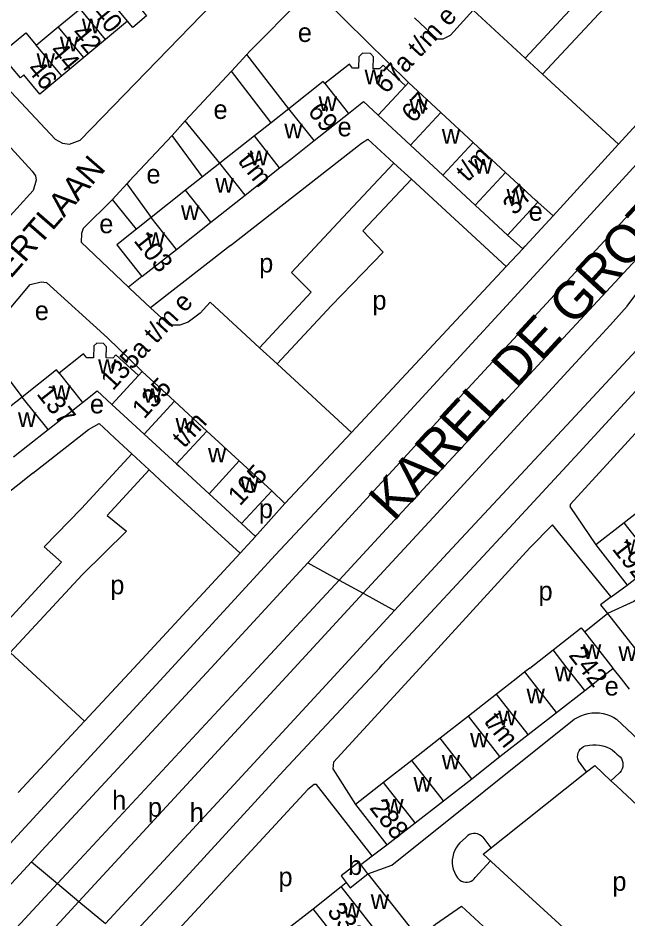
# Model space of a CAD drawing. Extents: x 159045 to 160918, y 380454 to 382516.
# Drawn here: x 159658 to 159786.4, y 381697.2 to 381886.8 of the extents above; entities that cross this region are included whole.
import ezdxf

# ---------------------------------------------------------------- set-up
doc = ezdxf.new("R2010")
doc.units = 0
for name, color, linetype in [('BLT_Basislijn', 7, 'Continuous'), ('BLT_Bebouwing', 7, 'Continuous'), ('BLT_Centroide', 7, 'Continuous'), ('BLT_Huisnummer', 7, 'Continuous'), ('BLT_Huisnummer_ tussenligend', 7, 'Continuous'), ('BLT_Huisnummer_reeks', 7, 'Continuous'), ('BLT_Onderverdeling_panden', 7, 'Continuous'), ('BLT_Straatnaam', 7, 'Continuous'), ('BLT_Straatnaam_hoofdweg', 7, 'Continuous'), ('BLT_Vlakafsluiter', 7, 'Continuous')]:
    doc.layers.add(name, color=color, linetype=linetype)

msp = doc.modelspace()

# ---------------------------------------------------------------- linework, layer by layer
at = {"layer": 'BLT_Basislijn'}
for p, q in [((159706.18, 381879.18), (159702.89, 381875.65)), ((159714.98, 381867.75), (159706.18, 381879.18)), ((159764.73, 381878.39), (159768.4, 381875)), ((159702.89, 381875.65), (159693.18, 381865.19)), ((159711.24, 381864.8), (159702.89, 381875.65)), ((159768.4, 381875), (159784.38, 381860.25)), ((159693.18, 381865.19), (159690.43, 381862.1)), ((159700.49, 381856.3), (159693.18, 381865.19)), ((159696.84, 381853.41), (159690.43, 381862.1)), ((159770.67, 381845.22), (159784.38, 381860.25)), ((159740.8, 381852.9), (159760.77, 381834.53)), ((159680.88, 381851.94), (159677.84, 381848.61)), ((159680.88, 381851.94), (159686, 381844.84)), ((159682.89, 381842.38), (159677.84, 381848.61)), ((159761.03, 381841.14), (159764.24, 381838.28)), ((159702.69, 381838.97), (159685.85, 381825.85)), ((159760.77, 381834.53), (159764.24, 381838.28)), ((159728.17, 381799.61), (159760.77, 381834.53)), ((159684.07, 381832.39), (159681.23, 381830.16)), ((159650.13, 381818.42), (159658.86, 381807.04)), ((159728.17, 381799.61), (159712.52, 381814.05)), ((159675.98, 381800.64), (159678.38, 381798.4)), ((159714.17, 381784.62), (159728.17, 381799.61)), ((159681.91, 381795.12), (159685.57, 381791.72)), ((159685.57, 381791.72), (159688.89, 381788.62)), ((159661.08, 381790.99), (159658.54, 381788.99)), ((159658.54, 381788.99), (159628.95, 381765.71)), ((159688.89, 381788.62), (159704.73, 381774.16)), ((159714.17, 381784.62), (159711.39, 381787.31)), ((159705.01, 381780.42), (159707.97, 381777.68)), ((159704.73, 381774.16), (159707.97, 381777.68)), ((159682.33, 381750), (159704.73, 381774.16)), ((159690.32, 381750), (159712.2, 381773.81)), ((159698.56, 381750), (159719, 381772.11)), ((159782.85, 381764.98), (159786.23, 381767.47)), ((159671.95, 381738.82), (159656.35, 381753.26)), ((159656.27, 381712.96), (159690.32, 381750)), ((159663, 381711.56), (159698.56, 381750)), ((159670.09, 381708.68), (159708.4, 381750)), ((159671.95, 381738.82), (159682.33, 381750)), ((159675.01, 381705.41), (159716.13, 381750)), ((159726.1, 381750), (159721.98, 381745.55)), ((159734.05, 381750), (159734.66, 381750.65)), ((159657.97, 381723.8), (159671.95, 381738.82)), ((159783.95, 381739.24), (159817.59, 381707.64)), ((159777.68, 381728.11), (159775.96, 381730.47)), ((159755.89, 381710.79), (159777.68, 381728.11)), ((159784.55, 381727.86), (159782.8, 381726.24)), ((159782.8, 381726.24), (159783.95, 381725.16)), ((159752.2, 381714.25), (159751.01, 381713.19)), ((159755.82, 381714.38), (159757.55, 381712.11)), ((159732.54, 381710.43), (159735.63, 381712.76)), ((159730.12, 381708.6), (159732.54, 381710.43)), ((159755.89, 381710.79), (159765.48, 381702.01)), ((159754.2, 381705.88), (159757.44, 381709.38))]:
    msp.add_line(p, q, dxfattribs=at)
for points in [[(159671.87, 381915.68), (159677.46, 381909.03), (159676.79, 381907.98), (159673.6, 381905.32), (159649.48, 381885.21), (159647.67, 381882.98), (159648.15, 381880.73), (159648.65, 381880.03), (159656.52, 381871.2), (159665.8, 381861.36), (159667.35, 381860.48), (159668.8, 381860.27), (159671.09, 381861.15), (159710.49, 381901.86), (159730.69, 381922.64), (159732.46, 381924.74), (159732.71, 381927.22), (159731.89, 381928.43)], [(159793.21, 381917.44), (159782.4, 381905.92), (159771.73, 381894.65), (159775.99, 381890.48), (159764.73, 381878.39)], [(159796.88, 381914.05), (159786.67, 381903.16), (159790.93, 381898.65), (159780.26, 381887.73), (159768.4, 381875)], [(159784.38, 381860.25), (159816.73, 381895.72)], [(159740.18, 381873.28), (159722.47, 381890.74), (159720.66, 381891.75), (159718.65, 381891.67), (159717.52, 381890.71), (159706.8, 381879.85), (159706.18, 381879.18)], [(159741.44, 381886.87), (159746.16, 381882.45), (159747.48, 381882.45), (159749.01, 381883.21), (159753.81, 381888.48), (159764.73, 381878.39)], [(159782.63, 381822.15), (159786.21, 381826.18), (159794.99, 381837.92), (159804.12, 381849.5), (159810.38, 381856.62), (159829.29, 381876.17), (159836.63, 381883.45)], [(159771.01, 381817.53), (159804.44, 381853.6), (159828.09, 381881.26)], [(159644.57, 381872.44), (159660.96, 381854.63), (159661.66, 381853.63), (159661.82, 381852.68), (159661.18, 381850.54), (159599.18, 381782.35), (159598.21, 381781.87), (159596.31, 381781.68), (159595.12, 381782.25), (159574.14, 381801.25), (159574.2, 381802.01), (159603.01, 381830.59)], [(159690.43, 381862.1), (159681.37, 381852.48), (159680.88, 381851.94)], [(159702.69, 381838.97), (159730.26, 381860.52), (159731.63, 381861.33), (159737.12, 381856.28)], [(159737.12, 381856.28), (159726.33, 381844.84), (159715.57, 381833.25), (159719.68, 381829.1), (159708.84, 381817.44)], [(159712.2, 381773.81), (159735.79, 381799.05), (159776.92, 381843.76), (159788.98, 381856.91)], [(159737.12, 381856.28), (159740.8, 381852.9)], [(159740.8, 381852.9), (159730.58, 381842.06), (159734.86, 381837.57), (159723.94, 381826.34), (159712.52, 381814.05)], [(159719, 381772.11), (159749.25, 381805.09), (159794.4, 381853.97)], [(159677.84, 381848.61), (159671.68, 381842.5), (159671.31, 381841.51), (159671.25, 381839.66), (159681.23, 381830.16)], [(159770.67, 381845.22), (159767.42, 381848.04)], [(159764.24, 381838.28), (159764.76, 381838.84), (159770.67, 381845.22)], [(159832.6, 381819.29), (159832.39, 381819.64), (159823.22, 381831.13), (159820.2, 381834.34), (159819.82, 381834.26), (159774.32, 381784.48), (159774.15, 381783.98), (159779.62, 381775.9)], [(159809.37, 381831.59), (159776.1, 381795.36), (159761.41, 381779.42), (159734.66, 381750.65)], [(159650.13, 381818.42), (159650.71, 381819.07), (159660.55, 381830.73), (159662.87, 381831.27), (159663.98, 381831.15), (159676.84, 381819.54), (159684.1, 381812.42)], [(159681.23, 381830.16), (159681.43, 381829.97), (159685.85, 381825.85)], [(159798.24, 381827.72), (159773.47, 381801.08), (159748.42, 381774.17), (159737.26, 381762.08)], [(159708.84, 381817.44), (159698.46, 381827.03), (159696.29, 381824.71), (159693.81, 381822.84), (159692.02, 381822.16), (159689.89, 381822.16), (159685.85, 381825.85)], [(159730.62, 381765.73), (159745.34, 381781.68), (159782.63, 381822.15)], [(159712.52, 381814.05), (159708.84, 381817.44)], [(159725.56, 381768.51), (159739.71, 381783.76), (159771.01, 381817.53)], [(159661.08, 381790.99), (159672.79, 381800.2), (159675.08, 381801.47), (159675.98, 381800.64)], [(159678.38, 381798.4), (159681.91, 381795.12)], [(159681.91, 381795.12), (159671.33, 381783.61), (159663.46, 381775.49), (159667.15, 381772.28), (159652.68, 381756.66)], [(159825.93, 381794.08), (159787.61, 381763.98), (159782.09, 381761.45)], [(159685.57, 381791.72), (159676.72, 381782.08), (159680.78, 381778.79), (159671.49, 381769.61), (159656.35, 381753.26)], [(159707.97, 381777.68), (159708.14, 381777.87), (159708.36, 381778.15), (159714.17, 381784.62)], [(159782.85, 381764.98), (159770.49, 381780.16), (159765.75, 381775.32), (159742.54, 381750)], [(159708.4, 381750), (159725.56, 381768.51)], [(159716.13, 381750), (159730.62, 381765.73)], [(159782.85, 381764.98), (159780.6, 381763.32), (159782.09, 381761.45)], [(159737.26, 381762.08), (159726.1, 381750)], [(159680.83, 381692.5), (159691.75, 381704.21), (159713.87, 381728.34), (159734.05, 381750)], [(159742.54, 381750), (159724.39, 381730.21), (159724.25, 381728.74), (159728.99, 381721.27)], [(159721.98, 381745.55), (159703.4, 381725.41), (159676.38, 381696.21)], [(159775.09, 381739.2), (159775.77, 381739.61), (159776.48, 381739.96), (159777.23, 381740.23), (159778.01, 381740.42), (159778.79, 381740.54), (159779.59, 381740.58), (159780.38, 381740.53), (159781.17, 381740.41), (159781.94, 381740.21), (159782.69, 381739.93), (159783.4, 381739.58), (159783.95, 381739.24)], [(159731.64, 381706.66), (159736.65, 381708.5), (159775.09, 381739.2)], [(159775.96, 381730.47), (159775.83, 381730.88), (159775.78, 381731.31), (159775.81, 381731.74), (159775.91, 381732.16), (159776.09, 381732.56), (159776.34, 381732.91), (159776.65, 381733.21), (159777.02, 381733.45), (159777.41, 381733.62), (159777.84, 381733.72), (159778.3, 381733.73)], [(159778.3, 381733.73), (159779, 381733.82), (159779.71, 381733.84), (159780.42, 381733.77), (159781.11, 381733.62), (159781.78, 381733.4), (159782.42, 381733.1), (159783.03, 381732.74), (159783.59, 381732.3), (159784.05, 381731.86)], [(159784.05, 381731.86), (159784.42, 381731.61), (159784.74, 381731.3), (159784.99, 381730.93), (159785.18, 381730.53), (159785.3, 381730.1), (159785.33, 381729.65), (159785.29, 381729.21), (159785.17, 381728.78), (159784.97, 381728.38), (159784.7, 381728.02), (159784.55, 381727.86)], [(159777.68, 381728.11), (159779.43, 381729.48), (159782.8, 381726.24)], [(159732.54, 381710.43), (159720.78, 381725.45), (159720.34, 381725.49), (159718.96, 381724.43), (159685.73, 381688.42)], [(159783.95, 381725.16), (159807.15, 381703.51), (159809.15, 381705.75)], [(159755.82, 381714.38), (159755.5, 381714.68), (159755.13, 381714.91), (159754.73, 381715.07), (159754.31, 381715.15), (159753.87, 381715.16), (159753.45, 381715.08), (159753.04, 381714.93), (159752.67, 381714.71), (159752.35, 381714.42), (159752.2, 381714.25)], [(159751.01, 381713.19), (159750.57, 381712.69), (159750.19, 381712.14), (159749.88, 381711.54), (159749.64, 381710.92), (159749.48, 381710.27), (159749.39, 381709.61), (159749.39, 381708.94), (159749.46, 381708.27), (159749.62, 381707.62), (159749.85, 381706.99), (159750.15, 381706.4), (159750.52, 381705.84), (159750.7, 381705.63)], [(159660.8, 381709.18), (159663, 381711.56)], [(159584.99, 381627.52), (159591.57, 381638.08), (159594.19, 381641.64), (159608.73, 381656.8), (159611.67, 381659.27), (159619.4, 381664.53), (159622.8, 381668.09), (159660.8, 381709.18)], [(159666.3, 381704.6), (159670.09, 381708.68)], [(159598.4, 381631.14), (159631.77, 381667.36), (159666.3, 381704.6)], [(159670.81, 381700.85), (159675.01, 381705.41)], [(159750.7, 381705.63), (159751, 381705.34), (159751.36, 381705.12), (159751.75, 381704.96), (159752.16, 381704.89), (159752.58, 381704.89), (159752.99, 381704.97), (159753.38, 381705.13), (159753.73, 381705.36), (159754.03, 381705.65), (159754.2, 381705.88)], [(159612.46, 381637.63), (159633.9, 381660.83), (159670.81, 381700.85)], [(159765.48, 381702.01), (159787.17, 381682.15), (159783.55, 381678.28)], [(159743.87, 381694.45), (159745.88, 381696.05), (159751.35, 381699.86), (159783.3, 381670.38)]]:
    msp.add_lwpolyline(points, dxfattribs=at)
at = {"layer": 'BLT_Bebouwing'}
for p, q in [((159666.43, 381884.96), (159671.05, 381888.8)), ((159661.81, 381881.12), (159666.43, 381884.96)), ((159681.04, 381886.18), (159676.42, 381882.34)), ((159676.42, 381882.34), (159671.8, 381878.5)), ((159671.8, 381878.5), (159667.17, 381874.66)), ((159740.18, 381873.28), (159739.52, 381872.57)), ((159746.99, 381866.97), (159740.18, 381873.28)), ((159714.98, 381867.75), (159711.24, 381864.8)), ((159720.29, 381861.03), (159727.54, 381866.76)), ((159733.79, 381866.38), (159740.6, 381860.07)), ((159753.8, 381860.66), (159746.99, 381866.97)), ((159711.24, 381864.8), (159707.73, 381862.03)), ((159707.73, 381862.03), (159700.49, 381856.3)), ((159740.6, 381860.07), (159747.41, 381853.76)), ((159760.61, 381854.35), (159753.8, 381860.66)), ((159700.49, 381856.3), (159696.84, 381853.41)), ((159705.81, 381849.58), (159713.05, 381855.3)), ((159766.9, 381848.52), (159760.61, 381854.35)), ((159696.84, 381853.41), (159693.25, 381850.57)), ((159693.25, 381850.57), (159686, 381844.84)), ((159698.56, 381843.85), (159705.81, 381849.58)), ((159767.42, 381848.04), (159766.9, 381848.52)), ((159754.22, 381847.45), (159761.03, 381841.14)), ((159761.03, 381841.14), (159767.42, 381848.04)), ((159686, 381844.84), (159682.89, 381842.38)), ((159691.32, 381838.12), (159698.56, 381843.85)), ((159684.07, 381832.39), (159691.32, 381838.12)), ((159684.1, 381812.42), (159683.31, 381811.57)), ((159690.92, 381806.15), (159684.1, 381812.42)), ((159658.86, 381807.04), (159655.21, 381804.14)), ((159664.29, 381800.2), (159671.52, 381805.93)), ((159677.74, 381805.5), (159684.55, 381799.23)), ((159697.74, 381799.88), (159690.92, 381806.15)), ((159684.55, 381799.23), (159691.37, 381792.96)), ((159704.56, 381793.61), (159697.74, 381799.88)), ((159711.39, 381787.31), (159704.56, 381793.61)), ((159698.19, 381786.69), (159705.01, 381780.42)), ((159705.01, 381780.42), (159711.39, 381787.31)), ((159791.49, 381785.21), (159785.56, 381780.55)), ((159785.56, 381780.55), (159779.62, 381775.9)), ((159779.62, 381775.9), (159786.23, 381767.47)), ((159786.23, 381767.47), (159792.17, 381772.12)), ((159777.2, 381757.63), (159782.09, 381761.45)), ((159782.09, 381761.45), (159791.05, 381750)), ((159765.76, 381750), (159770.63, 381753.81)), ((159765.76, 381750), (159764.68, 381749.16)), ((159758.73, 381744.51), (159752.79, 381739.86)), ((159771.33, 381740.64), (159777.28, 381745.29)), ((159765.38, 381735.99), (159771.33, 381740.64)), ((159752.79, 381739.86), (159746.84, 381735.21)), ((159746.84, 381735.21), (159740.89, 381730.56)), ((159759.43, 381731.35), (159765.38, 381735.99)), ((159753.48, 381726.7), (159759.43, 381731.35)), ((159740.89, 381730.56), (159734.94, 381725.92)), ((159734.94, 381725.92), (159728.99, 381721.27)), ((159747.53, 381722.06), (159753.48, 381726.7)), ((159741.58, 381717.41), (159747.53, 381722.06)), ((159728.99, 381721.27), (159735.63, 381712.76)), ((159735.63, 381712.76), (159741.58, 381717.41)), ((159731.64, 381706.66), (159730.12, 381708.6)), ((159731.64, 381706.66), (159741.09, 381694.67)), ((159726.02, 381703.97), (159727.09, 381704.81)), ((159720.1, 381699.33), (159726.02, 381703.97)), ((159714.17, 381694.69), (159720.1, 381699.33))]:
    msp.add_line(p, q, dxfattribs=at)
for points in [[(159685.67, 381890.03), (159683.94, 381888.59), (159685.04, 381887.27), (159682.15, 381884.87), (159681.04, 381886.18)], [(159667.17, 381874.66), (159662.55, 381870.82), (159659.21, 381874.85), (159658.49, 381874.26), (159656.61, 381876.52), (159654.29, 381879.31), (159659.62, 381883.75), (159661.81, 381881.12)], [(159739.52, 381872.57), (159734.84, 381876.91), (159734.1, 381876.11), (159732.77, 381876.15), (159732.84, 381878.68), (159732.18, 381879.37), (159730.52, 381879.41), (159729.73, 381878.66), (159729.67, 381876.26), (159728.39, 381876.29), (159727.73, 381877.12), (159722.57, 381873.04)], [(159722.57, 381873.04), (159722.22, 381873.48), (159714.98, 381867.75)], [(159727.54, 381866.76), (159730.69, 381869.25), (159733.79, 381866.38)], [(159713.05, 381855.3), (159715.38, 381857.15), (159720.29, 381861.03)], [(159747.41, 381853.76), (159748.28, 381852.96), (159754.22, 381847.45)], [(159682.89, 381842.38), (159678.76, 381839.11), (159684.07, 381832.39)], [(159683.31, 381811.57), (159678.58, 381815.92), (159677.94, 381815.22), (159676.54, 381815.27), (159676.62, 381817.64), (159675.97, 381818.33), (159674.54, 381818.38), (159673.93, 381817.8), (159673.84, 381815.27), (159672.45, 381815.31), (159671.77, 381816.17), (159666.63, 381812.1)], [(159666.63, 381812.1), (159666.1, 381812.77), (159658.86, 381807.04)], [(159671.52, 381805.93), (159674.61, 381808.38), (159677.74, 381805.5)], [(159657.05, 381794.46), (159660.03, 381796.82), (159664.29, 381800.2)], [(159691.37, 381792.96), (159691.92, 381792.46), (159698.19, 381786.69)], [(159770.63, 381753.81), (159776.56, 381758.45), (159777.2, 381757.63)], [(159777.28, 381745.29), (159780.42, 381747.74), (159783.23, 381749.93)], [(159783.23, 381749.93), (159784.94, 381747.74), (159786.65, 381745.55)], [(159764.68, 381749.16), (159762.87, 381747.74), (159758.73, 381744.51)], [(159730.12, 381708.6), (159729.69, 381709.14), (159725.98, 381706.23), (159727.09, 381704.81)], [(159727.09, 381704.81), (159727.92, 381703.75), (159731.64, 381706.66)]]:
    msp.add_lwpolyline(points, dxfattribs=at)
at = {"layer": 'BLT_Onderverdeling_panden'}
for p, q in [((159681.04, 381886.18), (159675.68, 381892.65)), ((159676.42, 381882.34), (159671.05, 381888.8)), ((159671.8, 381878.5), (159666.43, 381884.96)), ((159667.17, 381874.66), (159661.81, 381881.12)), ((159722.57, 381873.04), (159727.54, 381866.76)), ((159739.52, 381872.57), (159733.79, 381866.38)), ((159720.29, 381861.03), (159714.98, 381867.75)), ((159740.6, 381860.07), (159746.99, 381866.97)), ((159713.05, 381855.3), (159707.73, 381862.03)), ((159747.41, 381853.76), (159753.8, 381860.66)), ((159705.81, 381849.58), (159700.49, 381856.3)), ((159754.22, 381847.45), (159760.61, 381854.35)), ((159698.56, 381843.85), (159693.25, 381850.57)), ((159691.32, 381838.12), (159686, 381844.84)), ((159666.63, 381812.1), (159671.52, 381805.93)), ((159683.31, 381811.57), (159677.74, 381805.5)), ((159664.29, 381800.2), (159658.86, 381807.04)), ((159690.92, 381806.15), (159684.55, 381799.23)), ((159697.74, 381799.88), (159691.37, 381792.96)), ((159704.56, 381793.61), (159698.19, 381786.69)), ((159792.17, 381772.12), (159785.56, 381780.55)), ((159777.2, 381757.63), (159783.17, 381750)), ((159773.6, 381750), (159770.63, 381753.81)), ((159777.28, 381745.29), (159773.6, 381750)), ((159783.17, 381750), (159783.23, 381749.93)), ((159771.33, 381740.64), (159764.68, 381749.16)), ((159765.38, 381735.99), (159758.73, 381744.51)), ((159759.43, 381731.35), (159752.79, 381739.86)), ((159753.48, 381726.7), (159746.84, 381735.21)), ((159747.53, 381722.06), (159740.89, 381730.56)), ((159741.58, 381717.41), (159734.94, 381725.92)), ((159732.61, 381695.55), (159726.02, 381703.97)), ((159726.69, 381690.91), (159720.1, 381699.33))]:
    msp.add_line(p, q, dxfattribs=at)
at = {"layer": 'BLT_Vlakafsluiter'}
for p, q in [((159719, 381772.11), (159725.56, 381768.51)), ((159725.56, 381768.51), (159730.62, 381765.73)), ((159730.62, 381765.73), (159737.26, 381762.08)), ((159660.8, 381709.18), (159666.3, 381704.6)), ((159666.3, 381704.6), (159670.81, 381700.85)), ((159670.81, 381700.85), (159676.38, 381696.21))]:
    msp.add_line(p, q, dxfattribs=at)

# ---------------------------------------------------------------- texts
at = {"layer": 'BLT_Centroide'}
for s, p in [('w', (159671.42, 381883.64)), ('e', (159716.88, 381881.8)), ('w', (159666.8, 381879.81)), ('w', (159661.89, 381876.33)), ('w', (159730.93, 381872.91)), ('w', (159721.26, 381867.25)), ('w', (159740.39, 381866.69)), ('e', (159699.12, 381865.59)), ('w', (159714.02, 381861.53)), ('e', (159725.24, 381861.93)), ('w', (159747.2, 381860.38)), ('w', (159706.77, 381855.81)), ('w', (159754.02, 381854.06)), ('e', (159685.01, 381852)), ('w', (159699.52, 381850.06)), ('w', (159760.83, 381847.75)), ('w', (159692.28, 381844.34)), ('e', (159765.48, 381844.16)), ('e', (159675.08, 381841.54)), ('w', (159685.04, 381838.62)), ('p', (159708.74, 381833.27)), ('p', (159732.59, 381825.44)), ('e', (159661.5, 381823.25)), ('w', (159674.83, 381811.94)), ('w', (159665.19, 381806.47)), ('w', (159684.33, 381805.83)), ('e', (159673.11, 381803.6)), ('w', (159657.95, 381800.75)), ('w', (159691.14, 381799.55)), ('w', (159697.97, 381793.28)), ('w', (159704.8, 381787)), ('p', (159708.68, 381781.57)), ('w', (159785.89, 381774.02)), ('p', (159677.4, 381765.52)), ('p', (159767.56, 381764.23)), ('w', (159776.91, 381751.91)), ('w', (159784.38, 381751.5)), ('w', (159770.98, 381747.22)), ('e', (159781.48, 381744.2)), ('w', (159765.03, 381742.58)), ('w', (159759.08, 381737.92)), ('w', (159753.14, 381733.28)), ('w', (159747.19, 381728.64)), ('w', (159741.23, 381723.98)), ('h', (159677.78, 381720.19)), ('p', (159685.31, 381718.69)), ('h', (159694.12, 381717.61)), ('w', (159735.28, 381719.34)), ('b', (159727.47, 381706.44)), ('p', (159712.81, 381704.05)), ('p', (159783.1, 381703.09)), ('w', (159726.36, 381697.44)), ('w', (159732.23, 381699.28))]:
    msp.add_text(s, height=4, dxfattribs=at).set_placement(p)
at = {"layer": 'BLT_Huisnummer'}
for s, rotation, p in [('40', 309.7209, (159673.43, 381887.93)), ('46', 309.7229, (159659.69, 381875.94))]:
    msp.add_text(s, height=4, rotation=rotation, dxfattribs=at).set_placement(p)
at = {"layer": 'BLT_Huisnummer_ tussenligend'}
for s, p in [('42', (159669.04, 381883.5)), ('44', (159664.45, 381879.78))]:
    msp.add_text(s, height=4, rotation=309.7209, dxfattribs=at).set_placement(p)
at = {"layer": 'BLT_Huisnummer_reeks'}
for s, rotation, p in [('67a t/m e', 47.1858, (159735.46, 381870.7)), ('67', 47.1855, (159741.24, 381864.54)), ('69', 308.333, (159718.81, 381867.13)), ('t/m', 308.3371, (159704.1, 381856.72)), ('t/m', 47.1862, (159752.66, 381852.15)), ('37', 47.1811, (159762.55, 381845.14)), ('103', 308.3371, (159682.19, 381839.93)), ('135a t/m e', 47.3857, (159677.94, 381808.24)), ('135', 47.3926, (159684.52, 381802.26)), ('137', 308.4147, (159661.74, 381807.67)), ('t/m ', 47.3922, (159692.95, 381796.13)), ('105', 47.3881, (159704.7, 381783.96)), ('192', 308.0903, (159782.9, 381775.05)), ('242', 307.987, (159773.76, 381752.66)), ('t/m', 307.9862, (159755.92, 381738.74)), ('288', 307.9854, (159731.83, 381720.53)), ('338', 308.0639, (159722.89, 381698.67))]:
    msp.add_text(s, height=4, rotation=rotation, dxfattribs=at).set_placement(p)
at = {"layer": 'BLT_Straatnaam'}
msp.add_text('SCHUBERTLAAN', height=5, rotation=48.9522, dxfattribs=at).set_placement((159641.04, 381814.15))
at = {"layer": 'BLT_Straatnaam_hoofdweg'}
msp.add_text('KAREL DE GROTELAAN', height=8, rotation=47.388, dxfattribs=at).set_placement((159737.09, 381780.62))

doc.saveas('drawing.dxf')
